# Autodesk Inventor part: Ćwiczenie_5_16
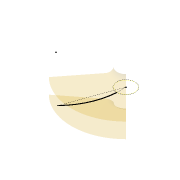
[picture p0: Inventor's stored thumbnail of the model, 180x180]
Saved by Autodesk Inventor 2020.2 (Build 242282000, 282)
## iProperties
Created: 2006-08
Part Number: Ćwiczenie_5_16
Document SubType Name: Modeling
Designer: F.Stasiak
Density: 1 g/cm^3
Material: Ogólny
Appearance: Domyślna
Manager: www.cadconsulting.pl
Company: Fabian Stasiak CAD Consulting
Author: F.Stasiak
Subject: Zbiór ćwiczeń. Autodesk Inventor 2020. Kurs podstawowy
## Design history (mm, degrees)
sketch "Szkic2"
  geometry: L1 (0, 0)-(250, 0); L2 (250, 0)-(250, 80); L3 (250, 80)-(0, 80); L4 (0, 80)-(0, 0); L5 (250, 40)-(66.797, 56.028); L6 (0, 0)-(0, -60); L7 (0, -60)-(250, -60); L8 (250, -60)-(250, 0); L9 (250, -30)-(62.582, -46.397); A1 r 30 centre (69.411, 85.914) between (40, 80) and (66.797, 56.028); A2 r 30 centre (65.197, -76.283) between (62.582, -46.397) and (40, -60)
  constraints: 18 end point, 4 point on circle, 3 parallel, 2 centre point, 2 midpoint, 2 perpendicular, 2 point on line, 2 tangent, 1 collinear, 1 horizontal
  dimensions: "d0" = 250 distance of L2.end L3.end; "d1" = 80 distance of L3.end L1.start; "d2" = 40 distance from line of L4 A1.start; "d3" = 5 deg angle of L5 L1; "d4" = 30 radius of A1; "d6" = 60 distance of L1.start L6.end; "d7" = 40 distance from line of L6 A2.end (= d2); "d8" = 5 deg angle of L1 L9; "d9" = 30 radius of A2
feature "PowObrotowa1" dims angle "d10" = 90 deg
feature "PowObrotowa2" dims angle "d11" = 90 deg
sketch "Szkic3" dims "d15" = 85
  geometry: L1 (0, 0)-(-230.225, 83.795); L2 (0, 0)-(-42.5, 0); L3 (-230.225, 83.795)-(-228.833, 85.231) reference; L4 (-42.5, 0)-(-42.5, 2.005); C1 r 40 at (0, 0) reference; A1 r 300 centre (-21.482, 299.263) between (-230.225, 83.795) and (-42.5, 0); A2 r 298 centre (-21.482, 299.263) between (-228.833, 85.231) and (-42.5, 2.005); 1 further point
  constraints: 8 end point, 4 point on circle, 2 centre point, 2 coincident, 1 horizontal, 1 horizontal alignment, 1 perpendicular, 1 vertical, 3 other
  dimensions: "d17" = 20 deg angle of L1 L2; "d18" = 300 radius of A1; "d19" = 2 radial gap between concentric circles of A2 A1
node "Korpusy bryłowe"
node "Korpusy powierzchniowe"
body "Srf1"
body "Srf2"
